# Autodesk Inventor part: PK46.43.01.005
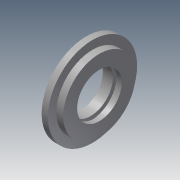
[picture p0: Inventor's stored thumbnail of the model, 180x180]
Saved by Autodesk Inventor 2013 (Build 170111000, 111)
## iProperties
Shininess: 64.0
Length Units: 11269
Angle Units: 11279
Time Units: 11290
Mass Units: 11283
Length Display Precision: 3
Angle Display Precision: 2
Compacted: True
Part Number: PK46.43.01.005
Document SubType Name: Modeling
Created: 2004-11
Material: Steel, High Strength Low Alloy
Designer: ELarisa
Manufacturer: Standard
Standards Organization: Custom
Density: 7.84 g/cm^3
Density: 0.0
Volumn: 0.0
Area: 0.0
PropertySet Name: Model Information
Control State: 0
Master: False
Checked Out: False
Checked Out Date: 2008-10-09
Last Check In Date: 2008-10-09
Author: ELarisa
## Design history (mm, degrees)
sketch "Эскиз1"
  geometry: L1 (-25.184, 0.049)-(-25.184, 45.049); L2 (-25.184, 45.049)-(-16.184, 45.049); L3 (-16.184, 45.049)-(-16.184, 71.049); L4 (-16.184, 71.049)-(-6.184, 71.049); L5 (-6.184, 71.049)-(-6.184, 57.549); L6 (-6.184, 57.549)-(4.816, 57.549); L7 (4.816, 57.549)-(4.816, 0.049); L8 (4.816, 0.049)-(-25.184, 0.049); L9 (-25.184, 35.549)-(-9.184, 35.549); L10 (-9.184, 35.549)-(-9.184, 42.099); L11 (-9.184, 42.099)-(-2.884, 42.099); L12 (-2.884, 42.099)-(-2.884, 35.549); L13 (-2.884, 35.549)-(4.816, 35.549)
  constraints: 26 end point, 9 parallel, 3 perpendicular, 2 point on line, 1 collinear, 1 vertical
  dimensions: "d0" = 30 distance of L7.end L1.start; "d1" = 14 distance between parallel lines of L7 L10; "d2" = 6.3 distance of L10.end L11.end; "d3" = 42.05 distance between parallel lines of L8 L11; "d4" = 71 distance between parallel lines of L8 L4; "d5" = 57.5 distance between parallel lines of L8 L6; "d6" = 45 distance between parallel lines of L8 L2; "d7" = 35.5 distance between parallel lines of L8 L13; "d8" = 9 distance of L1.end L2.end; "d9" = 19 distance between parallel lines of L5 L1
revolve "Вращение1" sketch "Эскиз1" stored, may be unused: angle "d10" = 90 deg
body "Solid1"
